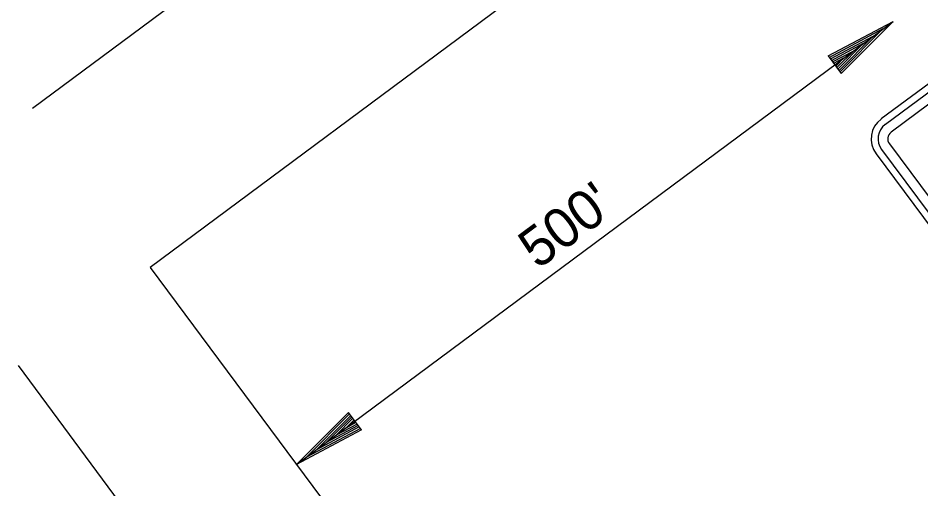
# Model space of a CAD drawing. Extents: x -238 to 1487, y -1123 to 446.
# Drawn here: x -115.7 to -6.3, y -592.5 to -535.5 of the extents above; entities that cross this region are included whole.
import ezdxf

# ---------------------------------------------------------------- set-up
doc = ezdxf.new("R2010")
doc.units = 0
for name, color, linetype in [('P_TC_Signs_Temporary', 7, 'Continuous'), ('R_Border Prem', 7, 'Continuous'), ('R_Draft', 7, 'Continuous')]:
    doc.layers.add(name, color=color, linetype=linetype)

msp = doc.modelspace()

# ---------------------------------------------------------------- linework, layer by layer
at = {"layer": 'P_TC_Signs_Temporary'}
for p, q in [((3.31, -536.98), (-11.14, -547.71)), ((3.81, -537.65), (-10.64, -548.38)), ((4.51, -538.58), (-9.95, -549.31)), ((-10.15, -550.71), (14.89, -584.43)), ((-11.76, -551.91), (13.28, -585.63)), ((-11.09, -551.41), (13.95, -585.13))]:
    msp.add_line(p, q, dxfattribs=at)
for radius in [3, 2.17, 1]:
    msp.add_arc((-9.35, -550.12), radius, 126.5953, 216.5953, dxfattribs=at)
at = {"layer": 'R_Draft'}
for p, q in [((24.57, -443.59), (-113.95, -546.45)), ((38.85, -462.81), (-99.68, -565.67)), ((-81.95, -589.54), (-9.7, -535.89)), ((-17.56, -540.08), (-9.7, -535.89)), ((-17.43, -540.26), (-10.89, -536.77)), ((-16.12, -542.02), (-10.89, -536.77)), ((-15.98, -542.2), (-9.7, -535.89)), ((-17.29, -540.44), (-12.1, -537.67)), ((-16.25, -541.84), (-12.1, -537.67)), ((-17.16, -540.61), (-13.28, -538.54)), ((-16.38, -541.67), (-13.28, -538.54)), ((-17.56, -540.08), (-15.98, -542.2)), ((-17.03, -540.8), (-14.47, -539.44)), ((-16.51, -541.49), (-14.47, -539.44)), ((-16.89, -540.97), (-15.65, -540.31)), ((-16.65, -541.31), (-15.65, -540.31)), ((-99.68, -565.67), (-65.48, -611.72)), ((-115.69, -577.56), (-81.5, -623.62)), ((-75.67, -583.23), (-81.95, -589.54)), ((-75.54, -583.41), (-80.77, -588.66)), ((-75.4, -583.59), (-79.55, -587.76)), ((-75.27, -583.76), (-78.37, -586.88)), ((-75.14, -583.94), (-77.18, -585.99)), ((-74.09, -585.35), (-75.67, -583.23)), ((-74.36, -584.99), (-79.55, -587.76)), ((-74.49, -584.82), (-78.37, -586.88)), ((-74.63, -584.63), (-77.18, -585.99)), ((-75, -584.12), (-76, -585.12)), ((-74.76, -584.46), (-76, -585.12)), ((-74.09, -585.35), (-81.95, -589.54)), ((-74.23, -585.17), (-80.77, -588.66))]:
    msp.add_line(p, q, dxfattribs=at)

# ---------------------------------------------------------------- texts
at = {"layer": 'R_Border Prem'}
for s, height, p in [("500'", 4.8, (-52.74, -565.99)), ('ADVANCE WARNING', 12, (-41.6, -679.12))]:
    msp.add_text(s, height=height, rotation=36.5953, dxfattribs=at).set_placement(p)

doc.saveas('drawing.dxf')
